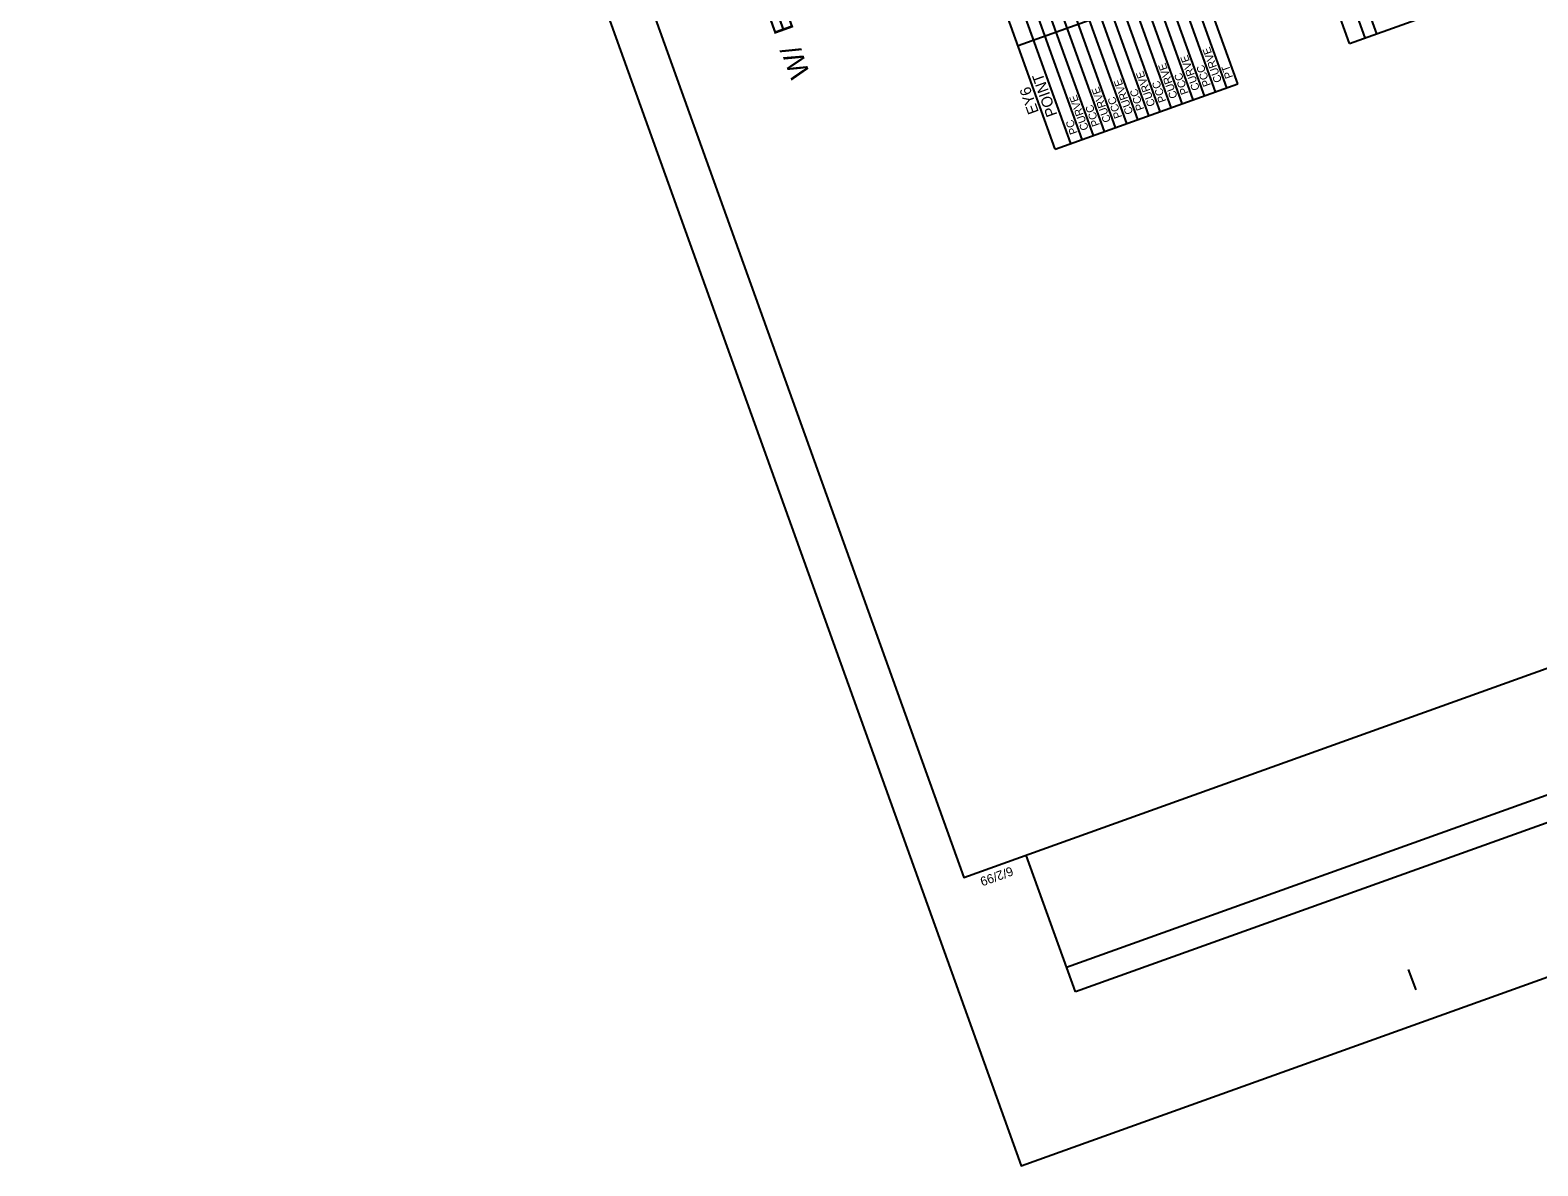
# Model space of a CAD drawing. Extents: x 480127 to 483680, y 514255 to 518588.
# Drawn here: x 480127 to 482044, y 514255 to 515699 of the extents above; entities that cross this region are included whole.
import ezdxf

# ---------------------------------------------------------------- set-up
doc = ezdxf.new("R2010")
doc.units = 0
for name, color, linetype in [('CTL Sheet Border CELL', 7, 'Continuous'), ('CTL Sheet Notes CELL', 7, 'Continuous'), ('CTL Sheet Table Cell', 7, 'Continuous'), ('CTL Sheet Text', 7, 'Continuous'), ('Sheet Block Revision CELL', 7, 'Continuous'), ('Sheet Plot Border Outside CELL', 7, 'Continuous')]:
    doc.layers.add(name, color=color, linetype=linetype)

msp = doc.modelspace()

# ---------------------------------------------------------------- linework, layer by layer
at = {"layer": 'CTL Sheet Border CELL'}
msp.add_line((481889.4, 514478.4), (481880, 514504.4), dxfattribs=at)
msp.add_lwpolyline([(480191.8, 517748), (481314.5, 514621.4), (483503, 515407.2), (482380.4, 518533.8)], close=True, dxfattribs=at)
at = {"layer": 'CTL Sheet Table Cell'}
for p, q in [((481805, 515682.4), (481331.9, 517000)), ((481824.8, 515689.5), (481351.7, 517007.1)), ((481839.4, 515694.7), (481366.3, 517012.3)), ((481648.6, 515626.1), (481175.5, 516943.8)), ((481662.7, 515631.2), (481189.6, 516948.8)), ((481592.1, 515605.9), (481119, 516923.5)), ((481606.2, 515610.9), (481133.1, 516928.6)), ((481620.3, 515616), (481147.2, 516933.6)), ((481634.4, 515621.1), (481161.3, 516938.7)), ((481549.7, 515590.7), (481076.6, 516908.3)), ((481563.9, 515595.7), (481090.8, 516913.4)), ((481578, 515600.8), (481104.9, 516918.4)), ((481493.3, 515570.4), (481020.2, 516888)), ((481507.4, 515575.4), (481034.3, 516893.1)), ((481521.5, 515580.5), (481048.4, 516898.2)), ((481535.6, 515585.6), (481062.5, 516903.2)), ((481430.7, 515547.9), (480957.6, 516865.5)), ((481450.4, 515555), (480977.3, 516872.6)), ((481465, 515560.2), (480991.9, 516877.9)), ((481479.1, 515565.3), (481006, 516882.9)), ((481383.4, 515679.7), (481615.4, 515763)), ((481805, 515682.4), (482008.8, 515755.5)), ((481430.7, 515547.9), (481662.7, 515631.2))]:
    msp.add_line(p, q, dxfattribs=at)
at = {"layer": 'Sheet Block Revision CELL'}
for p, q in [((483092.7, 515098.6), (481445.1, 514507)), ((483103.9, 515067.4), (481456.3, 514475.8)), ((481456.3, 514475.8), (481393.8, 514649.8))]:
    msp.add_line(p, q, dxfattribs=at)
at = {"layer": 'Sheet Plot Border Outside CELL'}
msp.add_lwpolyline([(483680.1, 515077.8), (482419.8, 518587.9), (480127, 517764.7), (481387.3, 514254.6)], close=True, dxfattribs=at)

# ---------------------------------------------------------------- texts
at = {"layer": 'CTL Sheet Border CELL'}
for s, height, rotation, p in [('W/  EXISTING CENTERLINE ALIGNMENTS PRIOR TO CONSTRUCTION', 25.469, 109.7508, (481119.1, 515643.5)), ('6/2/99', 11.63, 199.7508, (481374.6, 514635.6))]:
    msp.add_text(s, height=height, rotation=rotation, dxfattribs=at).set_placement(p)
at = {"layer": 'CTL Sheet Notes CELL'}
for s, p in [('POINT', (481433.4, 515592)), ('EY6', (481409.9, 515595.4))]:
    msp.add_text(s, height=14, rotation=109.7508, dxfattribs=at).set_placement(p)
at = {"layer": 'CTL Sheet Text'}
for s, p in [('CURVE', (481642.8, 515634.7)), ('CURVE', (481586.4, 515614.4)), ('CURVE', (481614.6, 515624.6)), ('CURVE', (481558.1, 515604.3)), ('PCC', (481600.5, 515619.5)), ('PCC', (481628.7, 515629.6)), ('PT', (481656.9, 515639.8)), ('CURVE', (481501.7, 515584)), ('CURVE', (481529.9, 515594.2)), ('PCC', (481544, 515599.2)), ('PCC', (481572.2, 515609.4)), ('CURVE', (481473.4, 515573.9)), ('PCC', (481487.5, 515578.9)), ('PCC', (481515.8, 515589.1)), ('PC', (481459.3, 515568.8))]:
    msp.add_text(s, height=10, rotation=109.7508, dxfattribs=at).set_placement(p)

doc.saveas('drawing.dxf')
